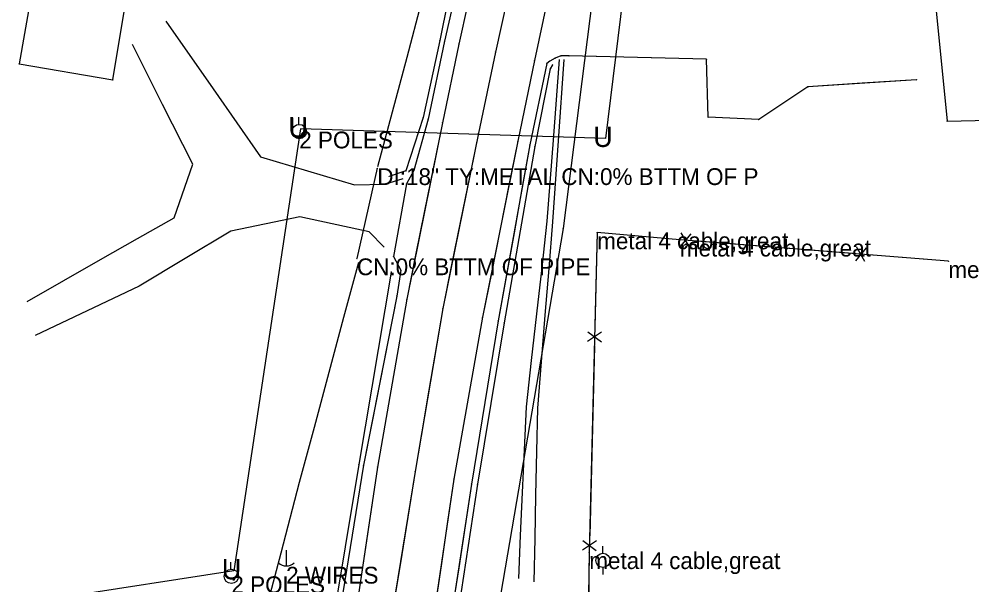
# Model space of a CAD drawing. Extents: x -99999 to 591807, y -99999 to 347168.
# Drawn here: x 590983 to 591266.7, y 322178.3 to 322346.6 of the extents above; entities that cross this region are included whole.
import ezdxf

# ---------------------------------------------------------------- set-up
doc = ezdxf.new("R2010")
doc.units = 0
for name, color, linetype in [('S_BREAKLINE', 7, 'Continuous'), ('S_BUILDING', 7, 'Continuous'), ('S_DITCHLINE', 7, 'Continuous'), ('S_DRG_PT_SYM', 7, 'Continuous'), ('S_DRIVEWAY', 7, 'Continuous'), ('S_EDGE_PAVEMENT', 7, 'Continuous'), ('S_FENCE', 7, 'Continuous'), ('S_FENCE_ANNOT', 7, 'Continuous'), ('S_GRD_PT_SYM', 7, 'Continuous'), ('S_MSC_PT_SYM', 7, 'Continuous'), ('S_PAVEMENT_CROWN', 7, 'Continuous'), ('S_RDW_PT_SYM', 7, 'Continuous'), ('S_SHOULDER', 7, 'Continuous'), ('S_SIDE_DRAIN', 7, 'Continuous'), ('S_SIDE_DRAIN_ANNOT', 7, 'Continuous'), ('S_STR_PT_SYM', 7, 'Continuous'), ('S_TELEPHONE_UTILITIES', 7, 'Continuous'), ('S_UNDERGROUND_CABLE', 7, 'Continuous'), ('S_UTILITY_POLE', 7, 'Continuous'), ('S_UTILITY_POLE_ANNOT', 7, 'Continuous'), ('S_UTL_PT_SYM', 7, 'Continuous'), ('S_WATER_UTILITIES', 7, 'Continuous')]:
    doc.layers.add(name, color=color, linetype=linetype)

msp = doc.modelspace()

# ---------------------------------------------------------------- linework, layer by layer
at = {"layer": 'S_BREAKLINE'}
for points in [[(591130.71, 322444.2), (591121.77, 322401.78), (591113.17, 322364.39), (591108.28, 322340.25), (591103.28, 322317.31), (591098.18, 322301.44), (591093.21, 322299.81)], [(591141.79, 322332.97), (591141.12, 322331.79), (591136.59, 322308.68), (591127.43, 322256.21), (591119.53, 322208.24), (591111.89, 322158.15), (591106.46, 322109.92), (591103.16, 322075.48), (591100.72, 322028.3), (591099.37, 321984.38), (591097.36, 321936.25)], [(591093.81, 322271.33), (591084.18, 322214.09), (591076.06, 322165.17), (591070.01, 322125.75)]]:
    msp.add_lwpolyline(points, dxfattribs=at)
at = {"layer": 'S_BUILDING'}
for p, q in [((590993.38, 322391.69), (590983.09, 322333.24)), ((591010.92, 322328.52), (591020.57, 322386.9)), ((591255.44, 322354.77), (591259.26, 322316.27)), ((590983.09, 322333.24), (591010.92, 322328.52)), ((591259.26, 322316.27), (591271.74, 322316.54))]:
    msp.add_line(p, q, dxfattribs=at)
at = {"layer": 'S_DITCHLINE'}
for points in [[(591125.46, 322447.34), (591124.89, 322436.59), (591120.66, 322432.18), (591119.1, 322429.93), (591116.09, 322414.36), (591113.08, 322398.8), (591110.07, 322383.24), (591107.07, 322367.68), (591102.74, 322351.41), (591098.41, 322335.14), (591094.08, 322318.88), (591089.75, 322302.61)], [(591143.84, 322334.56), (591141.99, 322310.54), (591140.14, 322286.52), (591138.6, 322272.71), (591137.05, 322258.91), (591135.51, 322245.1), (591133.97, 322231.29), (591133.39, 322218.52), (591132.81, 322205.75), (591132.23, 322192.98), (591131.66, 322180.2)], [(591145.19, 322334.59), (591143.49, 322310.43), (591141.8, 322286.28), (591140.68, 322272.42), (591139.56, 322258.56), (591138.43, 322244.7), (591137.31, 322230.84), (591137.05, 322217.95), (591136.79, 322205.05), (591136.52, 322192.16), (591136.26, 322179.27)], [(591084.06, 322274.2), (591079.65, 322257.85), (591075.24, 322241.5), (591070.83, 322225.16), (591066.42, 322208.81), (591060.93, 322187.76), (591055.44, 322166.71)]]:
    msp.add_lwpolyline(points, dxfattribs=at)
at = {"layer": 'S_DRG_PT_SYM'}
for points in [[(591089.67, 322302.24), (591089.67, 322302.29), (591089.67, 322302.24), (591089.62, 322302.24), (591089.67, 322302.24), (591089.67, 322302.19), (591089.67, 322302.24), (591089.72, 322302.24)], [(591083.61, 322275.42), (591083.61, 322275.47), (591083.61, 322275.42), (591083.56, 322275.42), (591083.61, 322275.42), (591083.61, 322275.37), (591083.61, 322275.42), (591083.66, 322275.42)]]:
    msp.add_lwpolyline(points, dxfattribs=at)
at = {"layer": 'S_DRIVEWAY'}
for points in [[(591026.72, 322345.99), (591040.8, 322325.81), (591054.87, 322305.63), (591068.88, 322301.46), (591082.89, 322297.3), (591091.95, 322297.49), (591097.38, 322299.16)], [(590985.43, 322262.58), (590996.37, 322268.81), (591007.32, 322275.05), (591018.26, 322281.29), (591029.21, 322287.52), (591034.76, 322303.44), (591025.77, 322321.22), (591016.78, 322339)], [(591250.11, 322328.57), (591217.83, 322326.4), (591203.2, 322316.7), (591188.1, 322317.44), (591187.62, 322334.66), (591146.69, 322335.66), (591144.32, 322335.64), (591142.56, 322334.93), (591140.98, 322334.12)], [(591250.11, 322328.57), (591233.97, 322327.49), (591217.83, 322326.4), (591203.2, 322316.7), (591188.1, 322317.44), (591187.62, 322334.66), (591167.15, 322335.16), (591146.69, 322335.66), (591144.32, 322335.64), (591142.56, 322334.93), (591140.98, 322334.12)], [(591091.74, 322278.71), (591087.23, 322283.34), (591066.58, 322287.78), (591046.06, 322283.54), (591032.44, 322275.37), (591018.81, 322267.2), (591003.33, 322259.83), (590987.85, 322252.45)]]:
    msp.add_lwpolyline(points, dxfattribs=at)
at = {"layer": 'S_EDGE_PAVEMENT'}
for points in [[(591155.01, 322516.17), (591143.09, 322467.79), (591137.43, 322444.09), (591127.36, 322400.1), (591119.29, 322363.42), (591113.95, 322339.18), (591109.05, 322315.77), (591098.43, 322263.26), (591089.75, 322213.36), (591082.38, 322164.3), (591076.73, 322114.81), (591073.7, 322079.67), (591071, 322030.35), (591070.29, 321986.98), (591070.69, 321935.66), (591071.05, 321919.08)], [(591177.24, 322510.33), (591165.63, 322463.26), (591159.78, 322438.95), (591149.6, 322395.03), (591141.62, 322358.52), (591136.41, 322334.23), (591131.46, 322310.28), (591121.02, 322257.9), (591112.47, 322209.78), (591105.04, 322159.54), (591099.44, 322110.84), (591096.78, 322076.76), (591094.19, 322028.58), (591093.31, 321985.65), (591093.42, 321935.97), (591093.55, 321920.04)], [(591149.05, 322491.98), (591143.09, 322467.79), (591137.43, 322444.09), (591132.4, 322422.09), (591127.36, 322400.1), (591123.33, 322381.76), (591119.29, 322363.42), (591113.95, 322339.18), (591109.05, 322315.77), (591106.39, 322302.64), (591103.74, 322289.52), (591101.08, 322276.39), (591098.43, 322263.26), (591096.26, 322250.79), (591094.09, 322238.31), (591091.92, 322225.83), (591089.75, 322213.36), (591086.07, 322188.83), (591082.38, 322164.3)], [(591171.44, 322486.8), (591165.63, 322463.26), (591162.71, 322451.11), (591159.78, 322438.95), (591154.69, 322416.99), (591149.6, 322395.03), (591145.61, 322376.77), (591141.62, 322358.52), (591136.41, 322334.23), (591131.46, 322310.28), (591128.85, 322297.19), (591126.24, 322284.09), (591123.63, 322270.99), (591121.02, 322257.9), (591116.75, 322233.84), (591112.47, 322209.78), (591110.61, 322197.22), (591108.76, 322184.66), (591106.9, 322172.1)]]:
    msp.add_lwpolyline(points, dxfattribs=at)
at = {"layer": 'S_FENCE'}
for p, q in [((591155.11, 322283.13), (591152.76, 322188.03)), ((591179.72, 322280.98), (591155.11, 322283.13)), ((591183.01, 322282.77), (591179.83, 322278.91)), ((591182.69, 322278.69), (591180.15, 322283)), ((591259.63, 322274.57), (591179.72, 322280.98)), ((591235.15, 322278.59), (591231.97, 322274.74)), ((591234.82, 322274.51), (591232.29, 322278.82)), ((591156.43, 322253.48), (591152.27, 322250.72)), ((591152.34, 322253.58), (591156.36, 322250.62)), ((591154.9, 322191.44), (591150.73, 322188.67)), ((591150.8, 322191.54), (591154.83, 322188.57)), ((591152.76, 322188.03), (591152, 322143.07))]:
    msp.add_line(p, q, dxfattribs=at)
for points in [[(591155.11, 322283.13), (591154.42, 322254.92)], [(591179.72, 322280.98), (591155.11, 322283.13)], [(591231.19, 322276.85), (591183.79, 322280.65)], [(591259.63, 322274.57), (591235.93, 322276.47)], [(591154.28, 322249.28), (591152.88, 322192.88)], [(591152.76, 322188.03), (591152, 322143.07)]]:
    msp.add_lwpolyline(points, dxfattribs=at)
at = {"layer": 'S_GRD_PT_SYM'}
for points in [[(591108.28, 322340.25), (591108.33, 322340.24), (591108.28, 322340.25), (591108.29, 322340.3), (591108.28, 322340.25), (591108.24, 322340.26), (591108.28, 322340.25), (591108.27, 322340.2)], [(591141.12, 322331.79), (591141.17, 322331.78), (591141.12, 322331.79), (591141.13, 322331.84), (591141.12, 322331.79), (591141.07, 322331.8), (591141.12, 322331.79), (591141.11, 322331.74)], [(591141.79, 322332.97), (591141.83, 322332.94), (591141.79, 322332.97), (591141.82, 322333.01), (591141.79, 322332.97), (591141.75, 322332.99), (591141.79, 322332.97), (591141.77, 322332.92)], [(591103.28, 322317.31), (591103.33, 322317.3), (591103.28, 322317.31), (591103.29, 322317.36), (591103.28, 322317.31), (591103.23, 322317.33), (591103.28, 322317.31), (591103.26, 322317.26)], [(591136.59, 322308.68), (591136.64, 322308.67), (591136.59, 322308.68), (591136.6, 322308.73), (591136.59, 322308.68), (591136.54, 322308.69), (591136.59, 322308.68), (591136.58, 322308.63)], [(591093.21, 322299.81), (591093.23, 322299.76), (591093.21, 322299.81), (591093.26, 322299.83), (591093.21, 322299.81), (591093.2, 322299.86), (591093.21, 322299.81), (591093.16, 322299.8)], [(591098.18, 322301.44), (591098.2, 322301.4), (591098.18, 322301.44), (591098.23, 322301.46), (591098.18, 322301.44), (591098.17, 322301.49), (591098.18, 322301.44), (591098.13, 322301.43)], [(591093.81, 322271.33), (591093.86, 322271.33), (591093.81, 322271.33), (591093.82, 322271.38), (591093.81, 322271.33), (591093.76, 322271.34), (591093.81, 322271.33), (591093.8, 322271.28)], [(591127.43, 322256.21), (591127.48, 322256.2), (591127.43, 322256.21), (591127.44, 322256.26), (591127.43, 322256.21), (591127.38, 322256.22), (591127.43, 322256.21), (591127.43, 322256.16)], [(591084.18, 322214.09), (591084.23, 322214.08), (591084.18, 322214.09), (591084.19, 322214.13), (591084.18, 322214.09), (591084.13, 322214.09), (591084.18, 322214.09), (591084.17, 322214.04)], [(591119.53, 322208.24), (591119.58, 322208.24), (591119.53, 322208.24), (591119.54, 322208.29), (591119.53, 322208.24), (591119.49, 322208.25), (591119.53, 322208.24), (591119.53, 322208.19)]]:
    msp.add_lwpolyline(points, close=True, dxfattribs=at)
at = {"layer": 'S_MSC_PT_SYM'}
for points in [[(591155.11, 322283.13), (591155.11, 322283.18), (591155.11, 322283.13), (591155.06, 322283.13), (591155.11, 322283.13), (591155.11, 322283.08), (591155.11, 322283.13), (591155.16, 322283.13)], [(591179.72, 322280.98), (591179.72, 322281.03), (591179.72, 322280.98), (591179.67, 322280.98), (591179.72, 322280.98), (591179.72, 322280.93), (591179.72, 322280.98), (591179.77, 322280.98)], [(591259.63, 322274.57), (591259.63, 322274.62), (591259.63, 322274.57), (591259.58, 322274.57), (591259.63, 322274.57), (591259.63, 322274.52), (591259.63, 322274.57), (591259.68, 322274.57)], [(591152.76, 322188.03), (591152.76, 322188.08), (591152.76, 322188.03), (591152.71, 322188.03), (591152.76, 322188.03), (591152.76, 322187.98), (591152.76, 322188.03), (591152.81, 322188.03)]]:
    msp.add_lwpolyline(points, dxfattribs=at)
at = {"layer": 'S_PAVEMENT_CROWN'}
for points in [[(591166.02, 322513.49), (591154.15, 322465.35), (591148.44, 322441.45), (591138.39, 322397.64), (591130.1, 322360.67), (591124.85, 322336.77), (591119.75, 322312.64), (591109.15, 322260.48), (591100.94, 322212.04), (591092.95, 322162.74), (591087.94, 322113.64), (591084.9, 322078.73), (591082.75, 322029.75), (591081.89, 321986.1), (591081.86, 321935.1), (591082.15, 321919.25)], [(591160.09, 322489.42), (591154.15, 322465.35), (591148.44, 322441.45), (591143.41, 322419.54), (591138.39, 322397.64), (591134.24, 322379.15), (591130.1, 322360.67), (591124.85, 322336.77), (591119.75, 322312.64), (591117.1, 322299.6), (591114.45, 322286.56), (591111.8, 322273.52), (591109.15, 322260.48), (591105.04, 322236.26), (591100.94, 322212.04), (591096.94, 322187.39), (591092.95, 322162.74)]]:
    msp.add_lwpolyline(points, dxfattribs=at)
at = {"layer": 'S_RDW_PT_SYM'}
for points in [[(591109.62, 322340), (591109.67, 322339.99), (591109.62, 322340), (591109.63, 322340.05), (591109.62, 322340), (591109.57, 322340.01), (591109.62, 322340), (591109.61, 322339.96)], [(591113.95, 322339.18), (591114, 322339.17), (591113.95, 322339.18), (591113.96, 322339.23), (591113.95, 322339.18), (591113.9, 322339.19), (591113.95, 322339.18), (591113.94, 322339.14)], [(591124.85, 322336.77), (591124.9, 322336.76), (591124.85, 322336.77), (591124.86, 322336.82), (591124.85, 322336.77), (591124.8, 322336.78), (591124.85, 322336.77), (591124.84, 322336.72)], [(591136.41, 322334.23), (591136.46, 322334.22), (591136.41, 322334.23), (591136.42, 322334.28), (591136.41, 322334.23), (591136.36, 322334.24), (591136.41, 322334.23), (591136.4, 322334.18)], [(591140.98, 322334.12), (591141, 322334.08), (591140.98, 322334.12), (591141.02, 322334.14), (591140.98, 322334.12), (591140.95, 322334.17), (591140.98, 322334.12), (591140.93, 322334.1)], [(591140.98, 322334.12), (591141.01, 322334.08), (591140.98, 322334.12), (591141.02, 322334.15), (591140.98, 322334.12), (591140.95, 322334.16), (591140.98, 322334.12), (591140.94, 322334.09)], [(591142.56, 322334.93), (591142.59, 322334.88), (591142.56, 322334.93), (591142.61, 322334.95), (591142.56, 322334.93), (591142.54, 322334.97), (591142.56, 322334.93), (591142.52, 322334.91)], [(591144.32, 322335.64), (591144.34, 322335.6), (591144.32, 322335.64), (591144.37, 322335.66), (591144.32, 322335.64), (591144.3, 322335.69), (591144.32, 322335.64), (591144.28, 322335.62)], [(591146.69, 322335.66), (591146.69, 322335.61), (591146.69, 322335.66), (591146.74, 322335.66), (591146.69, 322335.66), (591146.69, 322335.71), (591146.69, 322335.66), (591146.64, 322335.66)], [(591187.62, 322334.66), (591187.62, 322334.61), (591187.62, 322334.66), (591187.67, 322334.65), (591187.62, 322334.66), (591187.62, 322334.71), (591187.62, 322334.66), (591187.57, 322334.66)], [(591140.11, 322333.4), (591140.16, 322333.39), (591140.11, 322333.4), (591140.12, 322333.44), (591140.11, 322333.4), (591140.07, 322333.41), (591140.11, 322333.4), (591140.1, 322333.35)], [(591250.11, 322328.57), (591250.11, 322328.52), (591250.11, 322328.57), (591250.16, 322328.58), (591250.11, 322328.57), (591250.1, 322328.62), (591250.11, 322328.57), (591250.06, 322328.57)], [(591217.83, 322326.4), (591217.86, 322326.36), (591217.83, 322326.4), (591217.87, 322326.43), (591217.83, 322326.4), (591217.8, 322326.44), (591217.83, 322326.4), (591217.79, 322326.38)], [(591104.84, 322316.87), (591104.89, 322316.86), (591104.84, 322316.87), (591104.85, 322316.92), (591104.84, 322316.87), (591104.79, 322316.89), (591104.84, 322316.87), (591104.83, 322316.82)], [(591188.1, 322317.44), (591188.05, 322317.44), (591188.1, 322317.44), (591188.1, 322317.39), (591188.1, 322317.44), (591188.15, 322317.44), (591188.1, 322317.44), (591188.1, 322317.49)], [(591203.2, 322316.7), (591203.19, 322316.65), (591203.2, 322316.7), (591203.25, 322316.7), (591203.2, 322316.7), (591203.2, 322316.75), (591203.2, 322316.7), (591203.15, 322316.71)], [(591109.05, 322315.77), (591109.09, 322315.76), (591109.05, 322315.77), (591109.06, 322315.82), (591109.05, 322315.77), (591109, 322315.78), (591109.05, 322315.77), (591109.04, 322315.72)], [(591119.75, 322312.64), (591119.8, 322312.63), (591119.75, 322312.64), (591119.76, 322312.69), (591119.75, 322312.64), (591119.7, 322312.65), (591119.75, 322312.64), (591119.74, 322312.59)], [(591131.46, 322310.28), (591131.51, 322310.27), (591131.46, 322310.28), (591131.47, 322310.33), (591131.46, 322310.28), (591131.42, 322310.29), (591131.46, 322310.28), (591131.45, 322310.23)], [(591135.06, 322309.16), (591135.11, 322309.15), (591135.06, 322309.16), (591135.07, 322309.21), (591135.06, 322309.16), (591135.01, 322309.16), (591135.06, 322309.16), (591135.05, 322309.11)], [(591100.55, 322301.53), (591100.59, 322301.51), (591100.55, 322301.53), (591100.57, 322301.58), (591100.55, 322301.53), (591100.5, 322301.56), (591100.55, 322301.53), (591100.52, 322301.49)], [(591098.37, 322297.55), (591098.42, 322297.54), (591098.37, 322297.55), (591098.38, 322297.6), (591098.37, 322297.55), (591098.32, 322297.56), (591098.37, 322297.55), (591098.36, 322297.5)], [(591094.49, 322275.99), (591094.54, 322276.02), (591094.49, 322275.99), (591094.47, 322276.04), (591094.49, 322275.99), (591094.45, 322275.97), (591094.49, 322275.99), (591094.52, 322275.95)], [(591096.67, 322271.91), (591096.72, 322271.9), (591096.67, 322271.91), (591096.68, 322271.96), (591096.67, 322271.91), (591096.62, 322271.92), (591096.67, 322271.91), (591096.66, 322271.86)], [(591095.47, 322264.19), (591095.52, 322264.18), (591095.47, 322264.19), (591095.48, 322264.24), (591095.47, 322264.19), (591095.43, 322264.2), (591095.47, 322264.19), (591095.47, 322264.14)], [(591098.43, 322263.26), (591098.47, 322263.25), (591098.43, 322263.26), (591098.43, 322263.31), (591098.43, 322263.26), (591098.38, 322263.27), (591098.43, 322263.26), (591098.42, 322263.21)], [(591109.15, 322260.48), (591109.2, 322260.48), (591109.15, 322260.48), (591109.16, 322260.53), (591109.15, 322260.48), (591109.1, 322260.49), (591109.15, 322260.48), (591109.14, 322260.43)], [(591121.02, 322257.9), (591121.07, 322257.89), (591121.02, 322257.9), (591121.03, 322257.95), (591121.02, 322257.9), (591120.97, 322257.91), (591121.02, 322257.9), (591121.01, 322257.85)], [(591125.66, 322256.81), (591125.71, 322256.81), (591125.66, 322256.81), (591125.67, 322256.86), (591125.66, 322256.81), (591125.61, 322256.82), (591125.66, 322256.81), (591125.65, 322256.76)], [(591085.55, 322213.88), (591085.6, 322213.88), (591085.55, 322213.88), (591085.56, 322213.93), (591085.55, 322213.88), (591085.5, 322213.89), (591085.55, 322213.88), (591085.54, 322213.83)], [(591089.75, 322213.36), (591089.8, 322213.35), (591089.75, 322213.36), (591089.76, 322213.41), (591089.75, 322213.36), (591089.7, 322213.36), (591089.75, 322213.36), (591089.75, 322213.31)], [(591100.94, 322212.04), (591100.99, 322212.03), (591100.94, 322212.04), (591100.94, 322212.09), (591100.94, 322212.04), (591100.89, 322212.05), (591100.94, 322212.04), (591100.93, 322211.99)], [(591112.47, 322209.78), (591112.52, 322209.78), (591112.47, 322209.78), (591112.48, 322209.83), (591112.47, 322209.78), (591112.42, 322209.79), (591112.47, 322209.78), (591112.46, 322209.73)], [(591117.7, 322208.32), (591117.75, 322208.31), (591117.7, 322208.32), (591117.71, 322208.36), (591117.7, 322208.32), (591117.65, 322208.32), (591117.7, 322208.32), (591117.69, 322208.27)]]:
    msp.add_lwpolyline(points, close=True, dxfattribs=at)
at = {"layer": 'S_SHOULDER'}
for points in [[(591137.44, 322469.34), (591133.63, 322445.25), (591123.61, 322401.4), (591115.17, 322364.04), (591109.62, 322340), (591104.84, 322316.87), (591100.55, 322301.53), (591098.37, 322297.55), (591094.49, 322275.99), (591096.67, 322271.91), (591095.47, 322264.19), (591085.55, 322213.88), (591077.61, 322164.92), (591072.14, 322125.92), (591068.66, 322117.04)], [(591137.44, 322469.34), (591133.63, 322445.25), (591128.62, 322423.33), (591123.61, 322401.4), (591119.39, 322382.72), (591115.17, 322364.04), (591109.62, 322340), (591104.84, 322316.87), (591100.55, 322301.53), (591098.37, 322297.55), (591094.49, 322275.99), (591096.67, 322271.91), (591095.47, 322264.19), (591092.99, 322251.61), (591090.51, 322239.04), (591088.03, 322226.46), (591085.55, 322213.88), (591081.58, 322189.4), (591077.61, 322164.92), (591074.87, 322145.42), (591072.14, 322125.92), (591068.66, 322117.04)], [(591140.98, 322334.12), (591140.11, 322333.4), (591135.06, 322309.16), (591125.66, 322256.81), (591117.7, 322208.32), (591110.08, 322158.52), (591104.71, 322110.25), (591101.57, 322075.67), (591098.96, 322028.42), (591097.53, 321984.9), (591096.04, 321935.78), (591096.53, 321921.92), (591094.98, 321920.21)], [(591140.98, 322334.12), (591140.11, 322333.4), (591135.06, 322309.16), (591132.71, 322296.07), (591130.36, 322282.98), (591128.01, 322269.9), (591125.66, 322256.81), (591121.68, 322232.56), (591117.7, 322208.32), (591115.79, 322195.87), (591113.89, 322183.42), (591111.98, 322170.97)]]:
    msp.add_lwpolyline(points, dxfattribs=at)
at = {"layer": 'S_SIDE_DRAIN'}
msp.add_line((591089.67, 322302.24), (591083.61, 322275.42), dxfattribs=at)
at = {"layer": 'S_STR_PT_SYM'}
for points in [[(590983.09, 322333.24), (590983.09, 322333.29), (590983.09, 322333.24), (590983.04, 322333.24), (590983.09, 322333.24), (590983.09, 322333.19), (590983.09, 322333.24), (590983.14, 322333.24)], [(591010.92, 322328.52), (591010.92, 322328.57), (591010.92, 322328.52), (591010.87, 322328.52), (591010.92, 322328.52), (591010.92, 322328.47), (591010.92, 322328.52), (591010.97, 322328.52)], [(591259.26, 322316.27), (591259.26, 322316.32), (591259.26, 322316.27), (591259.21, 322316.27), (591259.26, 322316.27), (591259.26, 322316.22), (591259.26, 322316.27), (591259.31, 322316.27)]]:
    msp.add_lwpolyline(points, dxfattribs=at)
at = {"layer": 'S_TELEPHONE_UTILITIES'}
for p, q in [((591156.82, 322187.68), (591156.82, 322189.8)), ((591156.82, 322183.46), (591156.82, 322181.4))]:
    msp.add_line(p, q, dxfattribs=at)
msp.add_circle((591156.84, 322185.6), 2.11, dxfattribs=at)
at = {"layer": 'S_UNDERGROUND_CABLE'}
for p, q in [((591166.02, 322379.15), (591157.58, 322311.11)), ((591066.84, 322313.95), (591047.01, 322182.53)), ((591157.58, 322311.11), (591066.82, 322313.98)), ((591066.82, 322313.98), (591066.84, 322313.95)), ((591047.01, 322182.53), (590995.72, 322174.53))]:
    msp.add_line(p, q, dxfattribs=at)
at = {"layer": 'S_UTILITY_POLE'}
for p, q in [((591066.31, 322315.28), (591066.31, 322317.39)), ((591062.51, 322188.65), (591062.51, 322183.92)), ((591046.12, 322183), (591046.12, 322185.1))]:
    msp.add_line(p, q, dxfattribs=at)
for centre in [(591066.43, 322313.14), (591046.24, 322180.86)]:
    msp.add_circle(centre, 2.13, dxfattribs=at)
msp.add_arc((591062.58, 322187.35), 3.41, 226.3972, 313.6028, dxfattribs=at)
at = {"layer": 'S_UTL_PT_SYM'}
msp.add_lwpolyline([(591144.96, 322284.3), (591144.96, 322284.35), (591144.96, 322284.3), (591144.91, 322284.3), (591144.96, 322284.3), (591144.96, 322284.25), (591144.96, 322284.3), (591145.01, 322284.3)], dxfattribs=at)
at = {"layer": 'S_WATER_UTILITIES'}
for p, q in [((591155.4, 322366.54), (591144.96, 322284.3)), ((591144.96, 322284.3), (591120.97, 322143.98))]:
    msp.add_line(p, q, dxfattribs=at)

# ---------------------------------------------------------------- texts
at = {"layer": 'S_FENCE_ANNOT'}
for p in [(591155.11, 322278.13), (591179.72, 322275.98), (591259.63, 322269.57), (591152.76, 322183.03)]:
    msp.add_text('metal 4 cable,great', height=5, dxfattribs=at).set_placement(p)
at = {"layer": 'S_SIDE_DRAIN_ANNOT'}
for s, p in [('DI:18" TY:METAL CN:0% BTTM OF P', (591089.67, 322297.24)), ('CN:0% BTTM OF PIPE', (591083.61, 322270.42))]:
    msp.add_text(s, height=5, dxfattribs=at).set_placement(p)
at = {"layer": 'S_UTILITY_POLE_ANNOT'}
for s, p in [('2 POLES', (591066.43, 322308.14)), ('2 WIRES', (591062.53, 322178.7)), ('2 POLES', (591046.24, 322175.86))]:
    msp.add_text(s, height=5, dxfattribs=at).set_placement(p)
at = {"layer": 'S_UTL_PT_SYM'}
for p in [(591063.19, 322311.43), (591063.21, 322311.41), (591063.26, 322311.24), (591153.95, 322308.56), (591043.38, 322179.98)]:
    msp.add_text('U', height=6, rotation=360, dxfattribs=at).set_placement(p)

doc.saveas('drawing.dxf')
